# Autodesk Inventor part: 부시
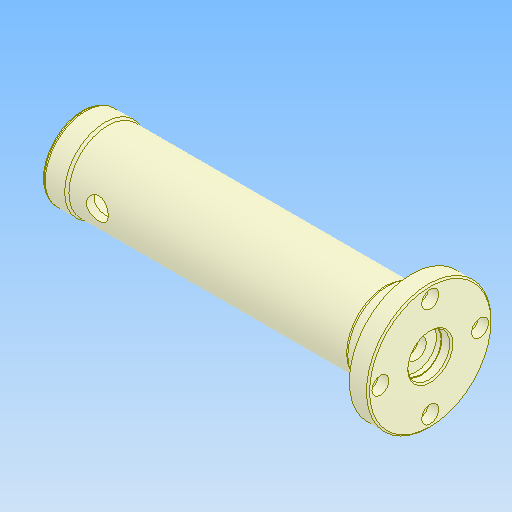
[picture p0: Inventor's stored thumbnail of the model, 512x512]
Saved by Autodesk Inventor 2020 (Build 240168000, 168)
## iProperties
Created: 2024-07
Part Number: 부시
Material: 강철, 탄소
Document SubType Name: Modeling
Designer: oem
Density: 7.85 g/cm^3
Appearance: 기본값
Author: jhkim
Sending System: Autodesk Inventor 2025
Preprocessor: ST-DEVELOPER v20
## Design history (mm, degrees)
feature "솔리드1"
node "솔리드2"
